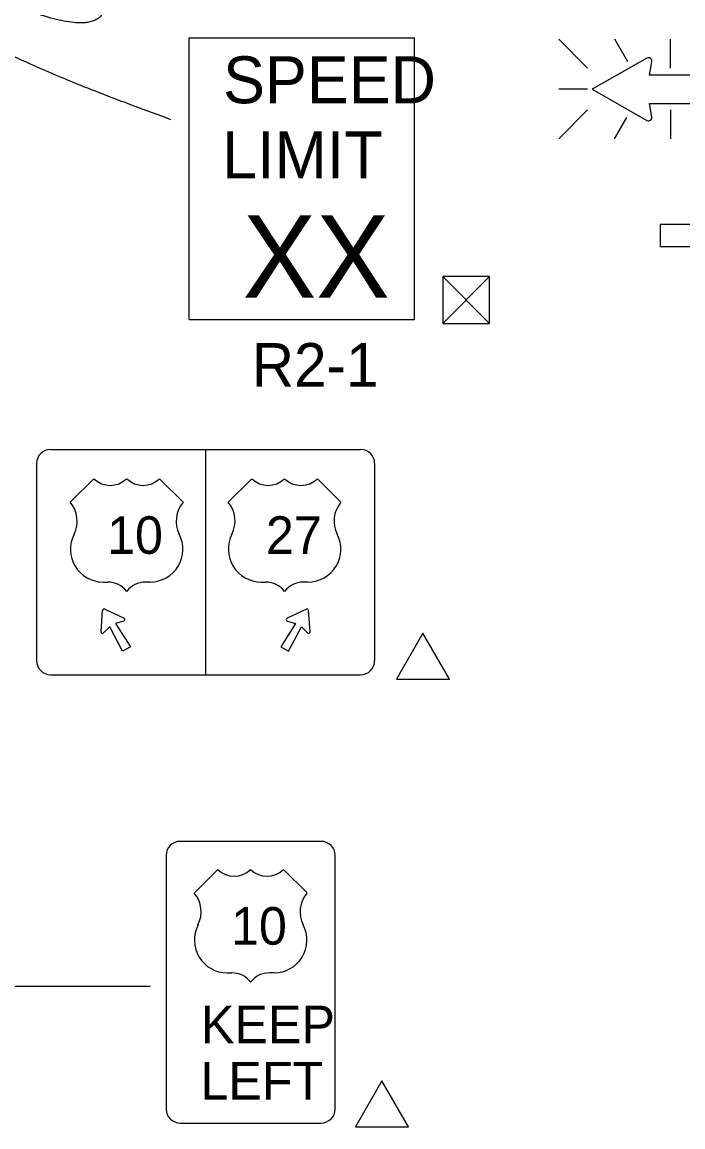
# Model space of a CAD drawing. Extents: x 16552 to 19508, y 5713 to 7079.
# Drawn here: x 17111.8 to 17224.3, y 6286.3 to 6474.6 of the extents above; entities that cross this region are included whole.
import ezdxf

# ---------------------------------------------------------------- set-up
doc = ezdxf.new("R2010")
doc.units = 0
for name, color, linetype in [('MT_SCRATCH_LEVEL_E', 7, 'Continuous'), ('PAVT_EDGE_EX', 7, 'Continuous'), ('TRAFFIC_SIGNS_PR', 7, 'Continuous'), ('TYPICAL_EX', 7, 'Continuous'), ('TYPICAL_TEXT_DIMEN_PR', 7, 'Continuous')]:
    doc.layers.add(name, color=color, linetype=linetype)

msp = doc.modelspace()

# ---------------------------------------------------------------- linework, layer by layer
at = {"layer": 'MT_SCRATCH_LEVEL_E'}
for p, q in [((17233.72, 6440.1), (17220.46, 6440.1)), ((17220.46, 6440.1), (17220.46, 6436.36)), ((17220.46, 6436.36), (17233.72, 6436.36))]:
    msp.add_line(p, q, dxfattribs=at)
at = {"layer": 'PAVT_EDGE_EX'}
for radius in [316, 300]:
    msp.add_arc((17319.93, 6383.76), radius, 107.923, 180, dxfattribs=at)
at = {"layer": 'TRAFFIC_SIGNS_PR'}
for p, q in [((17140.23, 6471.88), (17178.63, 6471.88)), ((17140.23, 6423.88), (17140.23, 6471.88)), ((17178.63, 6423.88), (17178.63, 6471.88)), ((17203.18, 6471.64), (17208.11, 6466.71)), ((17214.94, 6467.82), (17212.74, 6471.65)), ((17222.26, 6466.71), (17222.26, 6471.65)), ((17208.11, 6463.15), (17203.18, 6463.15)), ((17203.18, 6454.67), (17208.11, 6459.6)), ((17222.26, 6459.6), (17222.26, 6454.66)), ((17212.69, 6454.66), (17214.8, 6458.33)), ((17140.23, 6423.88), (17178.63, 6423.88)), ((17116.62, 6401.76), (17169.42, 6401.76)), ((17143.02, 6401.76), (17143.02, 6363.36)), ((17114.22, 6399.36), (17114.22, 6365.76)), ((17171.82, 6399.36), (17171.82, 6365.76)), ((17125.2, 6370.71), (17125.48, 6374.33)), ((17125.86, 6374.54), (17129.13, 6372.98)), ((17160.19, 6374.54), (17156.91, 6372.98)), ((17160.84, 6370.71), (17160.56, 6374.33)), ((17116.62, 6363.36), (17169.42, 6363.36)), ((17162.69, 6334.97), (17138.69, 6334.97)), ((17136.3, 6332.57), (17136.3, 6289.36)), ((17165.1, 6289.36), (17165.1, 6332.57)), ((17138.69, 6286.97), (17162.69, 6286.97))]:
    msp.add_line(p, q, dxfattribs=at)
for points in [[(17218.19, 6468.43), (17208.9, 6463.15), (17218.19, 6457.83)], [(17219.06, 6458.46), (17218.66, 6460.73), (17235.68, 6460.73), (17235.68, 6465.53), (17218.66, 6465.53), (17219.07, 6467.81)], [(17129.09, 6372.49), (17127.69, 6372.1), (17130.2, 6368.12), (17128.87, 6367.36), (17126.68, 6371.53), (17125.64, 6370.5)], [(17156.95, 6372.49), (17158.36, 6372.1), (17155.84, 6368.12), (17157.17, 6367.36), (17159.36, 6371.53), (17160.4, 6370.5)]]:
    msp.add_lwpolyline(points, dxfattribs=at)
for centre, radius, start, end in [((17218.48, 6467.91), 0.598, 350.7308, 118.8916), ((17218.48, 6458.36), 0.597, 241.4833, 9.9593), ((17116.62, 6399.36), 2.4, 90, 180), ((17116.62, 6399.36), 2.4, 90, 180), ((17169.42, 6399.36), 2.4, 0, 90), ((17125.74, 6374.31), 0.26, 64.4823, 175.5177), ((17129.02, 6372.74), 0.26, 285.9885, 64.4823), ((17157.02, 6372.74), 0.26, 115.5177, 254.0115), ((17160.3, 6374.31), 0.26, 4.4823, 115.5177), ((17125.46, 6370.69), 0.26, 175.5177, 314.0115), ((17160.58, 6370.69), 0.26, 225.9885, 4.4823), ((17116.62, 6365.76), 2.4, 180, 270), ((17169.42, 6365.76), 2.4, 270, 0), ((17138.69, 6332.57), 2.4, 90, 180), ((17162.69, 6332.57), 2.4, 0, 90), ((17138.69, 6289.37), 2.4, 180, 270), ((17162.69, 6289.37), 2.4, 270, 0)]:
    msp.add_arc(centre, radius, start, end, dxfattribs=at)
at = {"layer": 'TYPICAL_EX'}
for p, q in [((17119.97, 6392.76), (17123.97, 6396.76)), ((17139.17, 6392.76), (17135.17, 6396.76)), ((17146.87, 6392.76), (17150.87, 6396.76)), ((17166.07, 6392.76), (17162.07, 6396.76)), ((17125.57, 6379.15), (17126.37, 6379.15)), ((17133.58, 6379.15), (17132.78, 6379.15)), ((17152.47, 6379.15), (17153.27, 6379.15)), ((17160.48, 6379.15), (17159.68, 6379.15)), ((17141.1, 6326.17), (17145.1, 6330.17)), ((17160.3, 6326.17), (17156.3, 6330.17)), ((17146.69, 6312.56), (17147.49, 6312.56)), ((17154.7, 6312.56), (17153.9, 6312.56))]:
    msp.add_line(p, q, dxfattribs=at)
for centre, radius, start, end in [((17126.77, 6399.67), 4.04, 226.1404, 313.8596), ((17132.37, 6399.67), 4.04, 226.1404, 313.8596), ((17153.67, 6399.67), 4.04, 226.1404, 313.8596), ((17159.27, 6399.67), 4.04, 226.1404, 313.8596), ((17116.18, 6389.55), 4.96, 333.0977, 40.1936), ((17142.96, 6389.55), 4.96, 139.8064, 206.9023), ((17143.08, 6389.55), 4.96, 333.0977, 40.1936), ((17169.86, 6389.55), 4.96, 139.8064, 206.9023), ((17125.58, 6384.74), 5.59, 152.6698, 269.9013), ((17133.57, 6384.74), 5.59, 270.0987, 27.3302), ((17152.48, 6384.74), 5.59, 152.6698, 269.9013), ((17160.47, 6384.74), 5.59, 270.0987, 27.3302), ((17126.38, 6375.14), 4.01, 37.1038, 90.1385), ((17132.77, 6375.14), 4.01, 89.8615, 142.8962), ((17153.28, 6375.14), 4.01, 37.1038, 90.1385), ((17159.67, 6375.14), 4.01, 89.8615, 142.8962), ((17147.89, 6333.08), 4.04, 226.1404, 313.8596), ((17153.49, 6333.08), 4.04, 226.1404, 313.8596), ((17137.3, 6322.96), 4.96, 333.0977, 40.1936), ((17164.08, 6322.96), 4.96, 139.8064, 206.9023), ((17146.7, 6318.15), 5.59, 152.6698, 269.9013), ((17154.69, 6318.15), 5.59, 270.0987, 27.3302), ((17147.5, 6308.55), 4.01, 37.1038, 90.1385), ((17153.89, 6308.55), 4.01, 89.8615, 142.8962)]:
    msp.add_arc(centre, radius, start, end, dxfattribs=at)
at = {"layer": 'TYPICAL_TEXT_DIMEN_PR'}
for p, q in [((17183.42, 6431.2), (17191.42, 6423.2)), ((17183.42, 6423.2), (17191.42, 6431.2)), ((17133.57, 6310.21), (17094.37, 6310.21))]:
    msp.add_line(p, q, dxfattribs=at)
for points in [[(17183.42, 6431.2), (17183.42, 6423.2), (17191.42, 6423.2), (17191.42, 6431.2)], [(17180.05, 6370.43), (17175.53, 6362.59), (17184.58, 6362.59)], [(17173.06, 6294.14), (17168.54, 6286.31), (17177.59, 6286.31)]]:
    msp.add_lwpolyline(points, close=True, dxfattribs=at)
msp.add_arc((17319.93, 6383.76), 256, 137.0843, 167.0592, dxfattribs=at)
msp.add_open_spline([(17095.73, 6492.44), (17127.37, 6480.93), (17124.25, 6472.36), (17101.95, 6480.48), (17098.84, 6471.91), (17137.06, 6458)], degree=2, dxfattribs=at)

# ---------------------------------------------------------------- texts
at = {"layer": 'TRAFFIC_SIGNS_PR'}
for s, height, p in [('SPEED', 8, (17146, 6460.74)), ('LIMIT', 8, (17145.84, 6447.94)), ('XX', 14.031, (17149.35, 6427.64)), ('R2-1', 7.44, (17150.91, 6412.44)), ('10', 6.4, (17126.23, 6383.96)), ('27', 6.4, (17153.3, 6383.96)), ('10', 6.4, (17147.35, 6317.36)), ('KEEP', 6.4, (17142.23, 6300.57)), ('LEFT', 6.4, (17142.14, 6290.97))]:
    msp.add_text(s, height=height, dxfattribs=at).set_placement(p)

doc.saveas('drawing.dxf')
